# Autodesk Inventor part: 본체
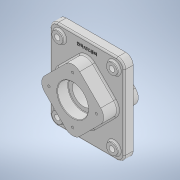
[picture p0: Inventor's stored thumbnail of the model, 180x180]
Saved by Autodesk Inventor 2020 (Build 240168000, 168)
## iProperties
Created: 2021-07
Part Number: 본체
Material: 일반
Document SubType Name: Modeling
Designer: Owner
Density: 1 g/cm^3
Appearance: 기본값
Mass: 807.977 g
Surface Area: 961.758 cm^2
Volume: 807.977 cm^3
Author: Owner
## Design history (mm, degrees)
sketch "스케치1"
  geometry: L1 (75, 90)-(-75, 90); L2 (-75, 90)-(-75, -90); L3 (-75, -90)-(75, -90); L4 (75, -90)-(75, 90); L5 (75, 90)-(-75, -90); L6 (-75, 90)-(75, -90); 1 further point
  constraints: 12 end point, 2 midpoint, 2 parallel, 1 horizontal, 1 perpendicular
  dimensions: "d0" = 150 distance of L1.start L1.end; "d1" = 180 distance between parallel lines of L3 L1
extrude "돌출1" new body sketch "스케치1" stored distance "d2" = 18; taper "d3" = 0 deg
sketch "스케치2"
  geometry: L1 (-56.569, 14.142)-(-14.142, 56.569); L2 (14.142, 56.569)-(56.569, 14.142); L3 (56.569, -14.142)-(14.142, -56.569); L4 (-14.142, -56.569)-(-56.569, -14.142); L5 (-70.711, 0)-(70.711, 0); L6 (0, 70.711)-(0, -70.711); A1 r 20 centre (0, 42.426) between (14.142, 56.569) and (-14.142, 56.569); A2 r 20 centre (42.426, 0) between (56.569, -14.142) and (56.569, 14.142); A3 r 20 centre (0, -42.426) between (-14.142, -56.569) and (14.142, -56.569); A4 r 20 centre (-42.426, 0) between (-56.569, 14.142) and (-56.569, -14.142); 1 further point
  constraints: 12 end point, 8 point on circle, 8 point on line, 8 tangent, 4 centre point, 3 equal radius, 2 midpoint, 2 parallel, 1 perpendicular, 1 vertical
  dimensions: "d4" = 100 distance of L6.start L5.end; "d5" = 45 deg angle of L6 L2; "d6" = 20 radius of A1
extrude "돌출2" join sketch "스케치2" distance "d7" = 29; taper "d8" = 0 deg
extrude "돌출3" join sketch "스케치2" distance "d9" = 41; taper "d10" = 0 deg
sketch "스케치3"
  geometry: L1 (0, 38)-(0, -32); L2 (-14.142, -32)-(14.142, -32) reference; L3 (56.569, 38)-(14.142, 38) reference; L4 (31, 38)-(31, 16); L5 (31, 16)-(22.5, 16); L6 (22.5, 16)-(22.5, -10); L7 (31, -10)-(31, -32); L8 (14.142, -32)-(56.569, -32) reference; L9 (31, -10)-(22.5, -10); L10 (14.142, 38)-(-14.142, 38) reference; 1 further point
  constraints: 12 end point, 4 point on line, 2 vertical, 1 midpoint, 1 perpendicular
  dimensions: "d11" = 62 diameter of L4 L1; "d12" = 45 diameter of L6 L1; "d13" = 22 distance between parallel lines of L5 L3; "d14" = 22 distance between parallel lines of L8 L9
revolve "회전1" sketch "스케치3" stored, may be unused: angle "d15" = 90 deg
fillet "모깎기1" dims "d16" = 15
sketch "스케치4"
  geometry: 2 further points
  constraints: 1 vertical alignment
  dimensions: "d17" = 48 distance of point (0, 0) point (0, 48)
hole "구멍1" sketch "스케치4" at (0, 48) diameter "d18" = 4.917; stored, may be unused: countersink angle "d22" = 90 deg, drill point angle "d24" = 118 deg; dims "d19" = 10, "d20" = 4, "d21" = 2, "d23" = 13
sketch "스케치5"
  geometry: 2 further points
  constraints: 1 vertical alignment
  dimensions: "d28" = 48 distance of point (0, 0) point (0, 48)
hole "구멍2" sketch "스케치5" at (0, 48) diameter "d29" = 4.917; stored, may be unused: countersink angle "d33" = 90 deg, drill point angle "d35" = 118 deg; dims "d30" = 10, "d31" = 4, "d32" = 2, "d34" = 13
sketch "스케치6"
  geometry: L1 (60, 90)-(-60, 90) reference; L2 (75, -75)-(75, 75) reference; L3 (-75, 75)-(-75, -75) reference; C1 r 11 at (55, 70); C2 r 11 at (-55, 70); 1 further point
  constraints: 2 centre point
  dimensions: "d39" = 22 diameter of C1; "d40" = 20 distance from line of L1 C1.centre; "d41" = 20 distance from line of L2 C1.centre; "d42" = 22 diameter of C2; "d43" = 110 distance of C1.centre C2.centre; "d44" = 20 distance from line of L3 C2.centre
extrude "돌출4" join sketch "스케치6" distance "d45" = 5; taper "d46" = 0 deg
sketch "스케치7"
  geometry: C1 r 11 at (0, 0) reference; 2 further points
  constraints: 1 coincident
hole "구멍3" sketch "스케치7" at (0, 0) diameter "d47" = 11; stored, may be unused: countersink angle "d51" = 90 deg, drill point angle "d53" = 0 deg; dims "d48" = 10, "d49" = 4, "d50" = 2, "d52" = 13
fillet "모깎기2" dims "d54" = 3
fillet "모깎기3" dims "d55" = 3
fillet "모깎기4" dims "d56" = 3
fillet "모깎기5" dims "d57" = 1
chamfer "모따기1" distance "d58" = 1; stored, may be unused: second distance "d59" = 2, angle "d60" = 45 deg
chamfer "모따기2" distance "d61" = 1; stored, may be unused: second distance "d62" = 2, angle "d63" = 45 deg
sketch "스케치8"
  geometry: L1 (60, 90)-(-60, 90) reference; 2 further points
  constraints: 1 vertical alignment, 1 other
  dimensions: "d64" = 15 distance from line of L1 point (0, 75)
feature "엠보싱1" sketch "스케치8" dims "d0" = 150, "d1" = 180, "d65" = 0.5, "d66" = 0
node "솔리드1"
pattern_circular "원형 패턴1" dims angle "d26" = 360 deg
pattern_circular "원형 패턴2" dims angle "d37" = 360 deg
mirror "미러1"
mirror "미러2"
mirror "미러3"
feature "A9D066F2-1C7D-4E18-AEED-F7BC21143FA4" dims "d47" = 11, "d48" = 10, "d49" = 4, "d50" = 2, "d51" = 90 deg, "d52" = 13, "d53" = 0
